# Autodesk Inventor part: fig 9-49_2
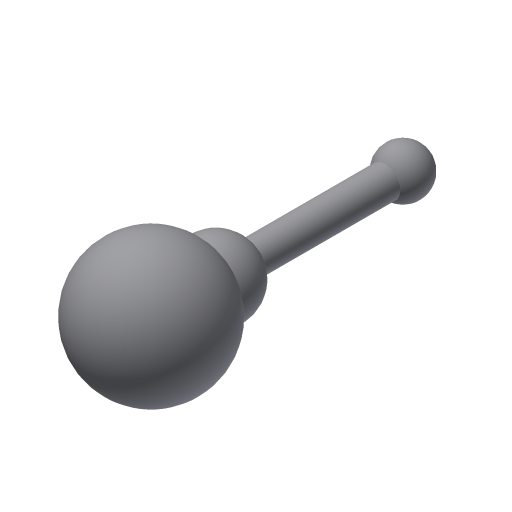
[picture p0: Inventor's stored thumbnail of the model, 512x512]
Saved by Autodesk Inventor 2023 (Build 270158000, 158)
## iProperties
Created: 2013-03
Part Number: fig 9-49_2
Material: Generic
Document SubType Name: Modeling
Designer: CADCIM
Density: 1 g/cm^3
Appearance: Default
Author: CADCIM
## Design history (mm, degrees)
sketch "Sketch1"
  geometry: L1 (0, 5)-(0, -5); A1 r 5 centre (0, 0) between (0, -5) and (0, 5); 1 further point
  constraints: 2 end point, 2 point on circle, 1 centre point, 1 coincident, 1 vertical
  dimensions: "d0" = 10 diameter of A1
revolve "Revolution1" sketch "Sketch1" stored, may be unused: angle "d2" = 90 deg
sketch "Sketch2"
  geometry: L1 (0, 20.921)-(0, 2.139); L2 (1.175, 7.426)-(1.175, 17.742); A1 r 1.807 centre (0, 19.115) between (1.175, 17.742) and (0, 20.921); A2 r 2.774 centre (0, 4.913) between (0, 2.139) and (1.175, 7.426); 1 further point
  constraints: 4 end point, 4 point on circle, 2 centre point, 1 parallel, 1 vertical
revolve "Revolution2" sketch "Sketch2" stored, may be unused: angle "d3" = 90 deg
body "Solid1"
